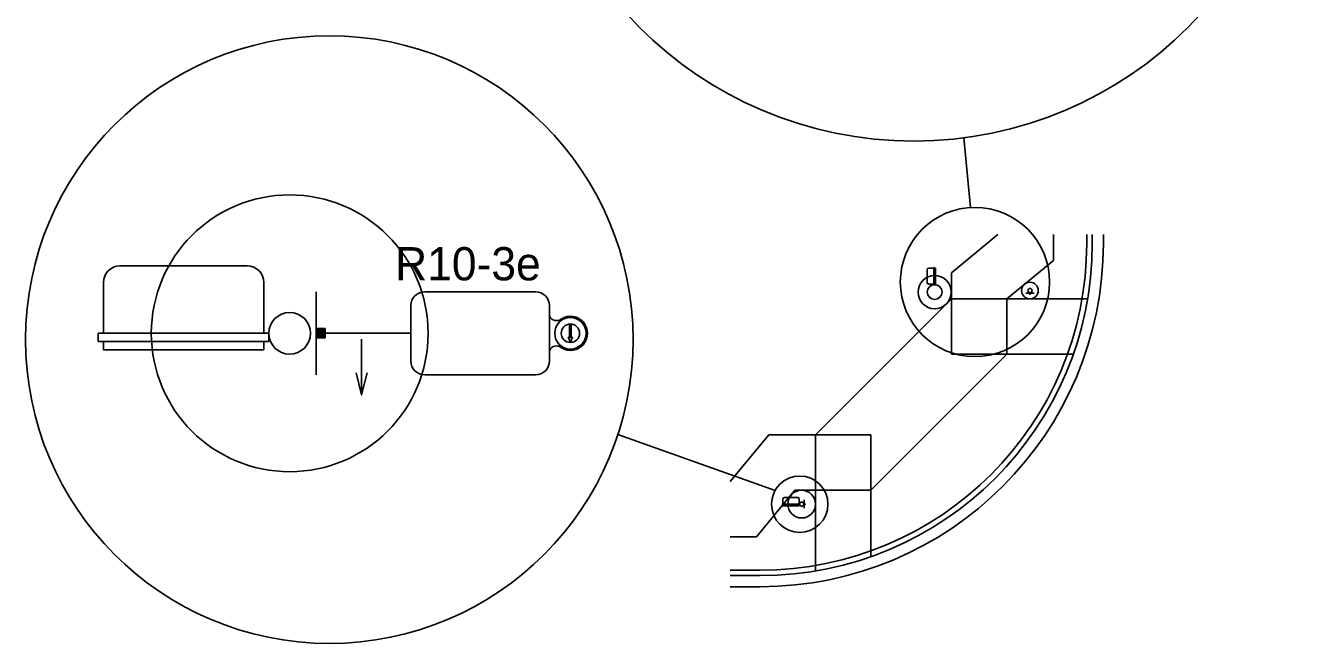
# Model space of a CAD drawing. Extents: x 1370050 to 1370716, y 380076 to 380502.
# Drawn here: x 1370417.2 to 1370532.5, y 380146.7 to 380202.5 of the extents above; entities that cross this region are included whole.
import ezdxf

# ---------------------------------------------------------------- set-up
doc = ezdxf.new("R2010")
doc.units = 0
doc.layers.add('T_Drafting', color=7, linetype='Continuous')

msp = doc.modelspace()

# ---------------------------------------------------------------- linework, layer by layer
at = {"layer": 'T_Drafting'}
for p, q in [((1370502.57, 380186.06), (1370501.97, 380192.36)), ((1370500.84, 380180.17), (1370505.04, 380183.62)), ((1370510.06, 380181.27), (1370510.06, 380183.62)), ((1370513.06, 380182.81), (1370513.06, 380183.62)), ((1370513.56, 380182.81), (1370513.56, 380183.62)), ((1370514.56, 380182.81), (1370514.56, 380183.62)), ((1370425.73, 380180.79), (1370437.23, 380180.79)), ((1370498.64, 380179.29), (1370498.64, 380180.44)), ((1370499.24, 380180.59), (1370498.79, 380180.59)), ((1370499.24, 380179.09), (1370499.24, 380180.63)), ((1370499.32, 380180.63), (1370499.24, 380180.63)), ((1370499.32, 380179.09), (1370499.32, 380180.63)), ((1370499.39, 380180.59), (1370499.32, 380180.59)), ((1370499.39, 380179.14), (1370499.39, 380180.59)), ((1370500.84, 380180.17), (1370500.84, 380172.81)), ((1370505.84, 380177.81), (1370510.06, 380181.27)), ((1370424.23, 380174.7), (1370424.23, 380179.29)), ((1370438.73, 380174.7), (1370438.73, 380179.29)), ((1370499.24, 380179.14), (1370498.79, 380179.14)), ((1370499.32, 380179.09), (1370499.24, 380179.09)), ((1370499.39, 380179.14), (1370499.32, 380179.14)), ((1370443.44, 380178.45), (1370443.44, 380170.95)), ((1370463.27, 380178.45), (1370453.26, 380178.45)), ((1370508.31, 380178.32), (1370507.56, 380178.32)), ((1370507.89, 380178.24), (1370507.89, 380178.32)), ((1370507.89, 380178.24), (1370507.97, 380178.32)), ((1370507.89, 380178.24), (1370507.97, 380178.32)), ((1370507.89, 380178.24), (1370507.97, 380178.32)), ((1370507.89, 380178.24), (1370507.97, 380178.32)), ((1370507.89, 380178.24), (1370507.97, 380178.32)), ((1370507.89, 380178.24), (1370507.97, 380178.32)), ((1370507.89, 380178.24), (1370507.97, 380178.32)), ((1370507.89, 380178.24), (1370507.97, 380178.32)), ((1370507.89, 380178.25), (1370507.97, 380178.32)), ((1370507.89, 380178.25), (1370507.96, 380178.32)), ((1370507.89, 380178.25), (1370507.96, 380178.32)), ((1370507.89, 380178.25), (1370507.96, 380178.32)), ((1370507.89, 380178.25), (1370507.96, 380178.32)), ((1370507.89, 380178.25), (1370507.96, 380178.32)), ((1370507.89, 380178.25), (1370507.96, 380178.32)), ((1370507.89, 380178.26), (1370507.96, 380178.32)), ((1370507.89, 380178.26), (1370507.95, 380178.32)), ((1370507.89, 380178.26), (1370507.95, 380178.32)), ((1370507.89, 380178.26), (1370507.95, 380178.32)), ((1370507.89, 380178.26), (1370507.95, 380178.32)), ((1370507.89, 380178.26), (1370507.95, 380178.32)), ((1370507.89, 380178.26), (1370507.95, 380178.32)), ((1370507.89, 380178.26), (1370507.95, 380178.32)), ((1370507.89, 380178.27), (1370507.94, 380178.32)), ((1370507.89, 380178.27), (1370507.94, 380178.32)), ((1370507.89, 380178.27), (1370507.94, 380178.32)), ((1370507.89, 380178.27), (1370507.94, 380178.32)), ((1370507.89, 380178.27), (1370507.94, 380178.32)), ((1370507.89, 380178.27), (1370507.94, 380178.32)), ((1370507.89, 380178.27), (1370507.94, 380178.32)), ((1370507.89, 380178.28), (1370507.93, 380178.32)), ((1370507.89, 380178.28), (1370507.93, 380178.32)), ((1370507.89, 380178.28), (1370507.93, 380178.32)), ((1370507.89, 380178.28), (1370507.93, 380178.32)), ((1370507.89, 380178.28), (1370507.93, 380178.32)), ((1370507.89, 380178.28), (1370507.93, 380178.32)), ((1370507.89, 380178.28), (1370507.93, 380178.32)), ((1370507.89, 380178.29), (1370507.92, 380178.32)), ((1370507.89, 380178.29), (1370507.92, 380178.32)), ((1370507.89, 380178.29), (1370507.92, 380178.32)), ((1370507.89, 380178.29), (1370507.92, 380178.32)), ((1370507.89, 380178.29), (1370507.92, 380178.32)), ((1370507.89, 380178.29), (1370507.92, 380178.32)), ((1370507.89, 380178.29), (1370507.92, 380178.32)), ((1370507.89, 380178.3), (1370507.91, 380178.32)), ((1370507.89, 380178.3), (1370507.91, 380178.32)), ((1370507.89, 380178.3), (1370507.91, 380178.32)), ((1370507.89, 380178.3), (1370507.91, 380178.32)), ((1370507.89, 380178.3), (1370507.91, 380178.32)), ((1370507.89, 380178.3), (1370507.91, 380178.32)), ((1370507.89, 380178.3), (1370507.91, 380178.32)), ((1370507.89, 380178.31), (1370507.91, 380178.32)), ((1370507.89, 380178.31), (1370507.9, 380178.32)), ((1370507.89, 380178.31), (1370507.9, 380178.32)), ((1370507.89, 380178.31), (1370507.9, 380178.32)), ((1370507.89, 380178.31), (1370507.9, 380178.32)), ((1370507.89, 380178.31), (1370507.9, 380178.32)), ((1370507.89, 380178.31), (1370507.9, 380178.32)), ((1370507.89, 380178.32), (1370507.9, 380178.32)), ((1370507.89, 380178.32), (1370507.89, 380178.32)), ((1370507.89, 380178.32), (1370507.89, 380178.32)), ((1370507.89, 380178.24), (1370507.97, 380178.24)), ((1370507.9, 380178.24), (1370507.97, 380178.32)), ((1370507.9, 380178.24), (1370507.97, 380178.31)), ((1370507.9, 380178.24), (1370507.97, 380178.31)), ((1370507.9, 380178.24), (1370507.97, 380178.31)), ((1370507.9, 380178.24), (1370507.97, 380178.31)), ((1370507.9, 380178.24), (1370507.97, 380178.31)), ((1370507.9, 380178.24), (1370507.97, 380178.31)), ((1370507.91, 380178.24), (1370507.97, 380178.31)), ((1370507.91, 380178.24), (1370507.97, 380178.3)), ((1370507.91, 380178.24), (1370507.97, 380178.3)), ((1370507.91, 380178.24), (1370507.97, 380178.3)), ((1370507.91, 380178.24), (1370507.97, 380178.3)), ((1370507.91, 380178.24), (1370507.97, 380178.3)), ((1370507.91, 380178.24), (1370507.97, 380178.3)), ((1370507.92, 380178.24), (1370507.97, 380178.3)), ((1370507.92, 380178.24), (1370507.97, 380178.29)), ((1370507.92, 380178.24), (1370507.97, 380178.29)), ((1370507.92, 380178.24), (1370507.97, 380178.29)), ((1370507.92, 380178.24), (1370507.97, 380178.29)), ((1370507.92, 380178.24), (1370507.97, 380178.29)), ((1370507.92, 380178.24), (1370507.97, 380178.29)), ((1370507.92, 380178.24), (1370507.97, 380178.29)), ((1370507.93, 380178.24), (1370507.97, 380178.28)), ((1370507.93, 380178.24), (1370507.97, 380178.28)), ((1370507.93, 380178.24), (1370507.97, 380178.28)), ((1370507.93, 380178.24), (1370507.97, 380178.28)), ((1370507.93, 380178.24), (1370507.97, 380178.28)), ((1370507.93, 380178.24), (1370507.97, 380178.28)), ((1370507.93, 380178.24), (1370507.97, 380178.28)), ((1370507.94, 380178.24), (1370507.97, 380178.27)), ((1370507.94, 380178.24), (1370507.97, 380178.27)), ((1370507.94, 380178.24), (1370507.97, 380178.27)), ((1370507.94, 380178.24), (1370507.97, 380178.27)), ((1370507.94, 380178.24), (1370507.97, 380178.27)), ((1370507.94, 380178.24), (1370507.97, 380178.27)), ((1370507.94, 380178.24), (1370507.97, 380178.27)), ((1370507.95, 380178.24), (1370507.97, 380178.26)), ((1370507.95, 380178.24), (1370507.97, 380178.26)), ((1370507.95, 380178.24), (1370507.97, 380178.26)), ((1370507.95, 380178.24), (1370507.97, 380178.26)), ((1370507.95, 380178.24), (1370507.97, 380178.26)), ((1370507.95, 380178.24), (1370507.97, 380178.26)), ((1370507.95, 380178.24), (1370507.97, 380178.26)), ((1370507.96, 380178.24), (1370507.97, 380178.25)), ((1370507.96, 380178.24), (1370507.97, 380178.25)), ((1370507.96, 380178.24), (1370507.97, 380178.25)), ((1370507.96, 380178.24), (1370507.97, 380178.25)), ((1370507.96, 380178.24), (1370507.97, 380178.25)), ((1370507.96, 380178.24), (1370507.97, 380178.25)), ((1370507.96, 380178.24), (1370507.97, 380178.25)), ((1370507.97, 380178.24), (1370507.97, 380178.32)), ((1370507.97, 380178.24), (1370507.97, 380178.25)), ((1370507.97, 380178.24), (1370507.97, 380178.24)), ((1370507.97, 380178.24), (1370507.97, 380178.24)), ((1370507.97, 380178.24), (1370507.97, 380178.24)), ((1370507.97, 380178.24), (1370507.97, 380178.24)), ((1370507.97, 380178.24), (1370507.97, 380178.24)), ((1370507.97, 380178.24), (1370507.97, 380178.24)), ((1370452.01, 380177.2), (1370452.01, 380172.2)), ((1370464.52, 380172.2), (1370464.52, 380177.2)), ((1370500.84, 380177.81), (1370488.56, 380165.52)), ((1370500.84, 380177.81), (1370513.14, 380177.81)), ((1370505.84, 380177.81), (1370505.84, 380172.81)), ((1370423.77, 380174.7), (1370439.19, 380174.7)), ((1370423.77, 380173.95), (1370423.77, 380174.7)), ((1370439.19, 380173.95), (1370439.19, 380174.7)), ((1370444.27, 380175.12), (1370443.44, 380175.12)), ((1370443.44, 380174.29), (1370444.27, 380175.12)), ((1370443.44, 380174.3), (1370444.26, 380175.12)), ((1370443.44, 380174.32), (1370444.24, 380175.12)), ((1370443.44, 380174.33), (1370444.23, 380175.12)), ((1370443.44, 380174.35), (1370444.21, 380175.12)), ((1370443.44, 380174.36), (1370444.2, 380175.12)), ((1370443.44, 380174.37), (1370444.18, 380175.12)), ((1370443.44, 380174.39), (1370444.17, 380175.12)), ((1370443.44, 380174.4), (1370444.16, 380175.12)), ((1370443.44, 380174.42), (1370444.14, 380175.12)), ((1370443.44, 380174.43), (1370444.13, 380175.12)), ((1370443.44, 380174.44), (1370444.11, 380175.12)), ((1370443.44, 380174.46), (1370444.1, 380175.12)), ((1370443.44, 380174.47), (1370444.09, 380175.12)), ((1370443.44, 380174.49), (1370444.07, 380175.12)), ((1370443.44, 380174.5), (1370444.06, 380175.12)), ((1370443.44, 380174.51), (1370444.04, 380175.12)), ((1370443.44, 380174.53), (1370444.03, 380175.12)), ((1370443.44, 380174.54), (1370444.01, 380175.12)), ((1370443.44, 380174.56), (1370444, 380175.12)), ((1370443.44, 380174.57), (1370443.99, 380175.12)), ((1370443.44, 380174.59), (1370443.97, 380175.12)), ((1370443.44, 380174.6), (1370443.96, 380175.12)), ((1370443.44, 380174.61), (1370443.94, 380175.12)), ((1370443.44, 380174.63), (1370443.93, 380175.12)), ((1370443.44, 380174.64), (1370443.92, 380175.12)), ((1370443.44, 380174.66), (1370443.9, 380175.12)), ((1370443.44, 380174.67), (1370443.89, 380175.12)), ((1370443.44, 380174.68), (1370443.87, 380175.12)), ((1370443.44, 380174.7), (1370443.86, 380175.12)), ((1370443.44, 380174.71), (1370443.84, 380175.12)), ((1370443.44, 380174.73), (1370443.83, 380175.12)), ((1370443.44, 380174.74), (1370443.82, 380175.12)), ((1370443.44, 380174.76), (1370443.8, 380175.12)), ((1370443.44, 380174.77), (1370443.79, 380175.12)), ((1370443.44, 380174.78), (1370443.77, 380175.12)), ((1370443.44, 380174.8), (1370443.76, 380175.12)), ((1370443.44, 380174.81), (1370443.75, 380175.12)), ((1370443.44, 380174.83), (1370443.73, 380175.12)), ((1370443.44, 380174.84), (1370443.72, 380175.12)), ((1370443.44, 380174.85), (1370443.7, 380175.12)), ((1370443.44, 380174.87), (1370443.69, 380175.12)), ((1370443.44, 380174.88), (1370443.68, 380175.12)), ((1370443.44, 380174.9), (1370443.66, 380175.12)), ((1370443.44, 380174.91), (1370443.65, 380175.12)), ((1370443.44, 380174.92), (1370443.63, 380175.12)), ((1370443.44, 380174.94), (1370443.62, 380175.12)), ((1370443.44, 380174.95), (1370443.6, 380175.12)), ((1370443.44, 380174.97), (1370443.59, 380175.12)), ((1370443.44, 380174.98), (1370443.58, 380175.12)), ((1370443.44, 380175), (1370443.56, 380175.12)), ((1370443.44, 380175.01), (1370443.55, 380175.12)), ((1370443.44, 380175.02), (1370443.53, 380175.12)), ((1370443.44, 380175.04), (1370443.52, 380175.12)), ((1370443.44, 380175.05), (1370443.51, 380175.12)), ((1370443.44, 380175.07), (1370443.49, 380175.12)), ((1370443.44, 380175.08), (1370443.48, 380175.12)), ((1370443.44, 380175.09), (1370443.46, 380175.12)), ((1370443.44, 380175.11), (1370443.45, 380175.12)), ((1370443.45, 380174.29), (1370444.27, 380175.11)), ((1370443.46, 380174.29), (1370444.27, 380175.09)), ((1370443.48, 380174.29), (1370444.27, 380175.08)), ((1370443.49, 380174.29), (1370444.27, 380175.07)), ((1370443.51, 380174.29), (1370444.27, 380175.05)), ((1370443.52, 380174.29), (1370444.27, 380175.04)), ((1370443.53, 380174.29), (1370444.27, 380175.02)), ((1370443.55, 380174.29), (1370444.27, 380175.01)), ((1370443.56, 380174.29), (1370444.27, 380174.99)), ((1370443.58, 380174.29), (1370444.27, 380174.98)), ((1370443.59, 380174.29), (1370444.27, 380174.97)), ((1370443.61, 380174.29), (1370444.27, 380174.95)), ((1370443.62, 380174.29), (1370444.27, 380174.94)), ((1370443.63, 380174.29), (1370444.27, 380174.92)), ((1370443.65, 380174.29), (1370444.27, 380174.91)), ((1370443.66, 380174.29), (1370444.27, 380174.9)), ((1370443.68, 380174.29), (1370444.27, 380174.88)), ((1370443.69, 380174.29), (1370444.27, 380174.87)), ((1370443.7, 380174.29), (1370444.27, 380174.85)), ((1370443.72, 380174.29), (1370444.27, 380174.84)), ((1370443.73, 380174.29), (1370444.27, 380174.82)), ((1370443.75, 380174.29), (1370444.27, 380174.81)), ((1370443.76, 380174.29), (1370444.27, 380174.8)), ((1370443.78, 380174.29), (1370444.27, 380174.78)), ((1370443.79, 380174.29), (1370444.27, 380174.77)), ((1370443.8, 380174.29), (1370444.27, 380174.75)), ((1370443.82, 380174.29), (1370444.27, 380174.74)), ((1370443.83, 380174.29), (1370444.27, 380174.73)), ((1370443.85, 380174.29), (1370444.27, 380174.71)), ((1370443.86, 380174.29), (1370444.27, 380174.7)), ((1370443.87, 380174.29), (1370444.27, 380174.68)), ((1370443.89, 380174.29), (1370444.27, 380174.67)), ((1370443.9, 380174.29), (1370444.27, 380174.66)), ((1370443.92, 380174.29), (1370444.27, 380174.64)), ((1370443.93, 380174.29), (1370444.27, 380174.63)), ((1370443.95, 380174.29), (1370444.27, 380174.61)), ((1370443.96, 380174.29), (1370444.27, 380174.6)), ((1370443.97, 380174.29), (1370444.27, 380174.58)), ((1370443.99, 380174.29), (1370444.27, 380174.57)), ((1370444, 380174.29), (1370444.27, 380174.56)), ((1370444.02, 380174.29), (1370444.27, 380174.54)), ((1370444.03, 380174.29), (1370444.27, 380174.53)), ((1370444.04, 380174.29), (1370444.27, 380174.51)), ((1370444.06, 380174.29), (1370444.27, 380174.5)), ((1370444.07, 380174.29), (1370444.27, 380174.49)), ((1370444.09, 380174.29), (1370444.27, 380174.47)), ((1370444.1, 380174.29), (1370444.27, 380174.46)), ((1370444.11, 380174.29), (1370444.27, 380174.44)), ((1370444.13, 380174.29), (1370444.27, 380174.43)), ((1370444.14, 380174.29), (1370444.27, 380174.41)), ((1370444.27, 380174.29), (1370444.27, 380175.12)), ((1370444.27, 380174.7), (1370452.01, 380174.7)), ((1370466.35, 380175.53), (1370466.5, 380175.53)), ((1370466.35, 380174.27), (1370466.35, 380175.53)), ((1370466.5, 380174.27), (1370466.5, 380175.53)), ((1370423.77, 380173.95), (1370439.19, 380173.95)), ((1370424.23, 380173.2), (1370424.23, 380173.95)), ((1370438.73, 380173.2), (1370438.73, 380173.95)), ((1370444.27, 380174.29), (1370443.44, 380174.29)), ((1370444.16, 380174.29), (1370444.27, 380174.4)), ((1370444.17, 380174.29), (1370444.27, 380174.39)), ((1370444.19, 380174.29), (1370444.27, 380174.37)), ((1370444.2, 380174.29), (1370444.27, 380174.36)), ((1370444.21, 380174.29), (1370444.27, 380174.34)), ((1370444.23, 380174.29), (1370444.27, 380174.33)), ((1370444.24, 380174.29), (1370444.27, 380174.32)), ((1370444.26, 380174.29), (1370444.27, 380174.3)), ((1370444.27, 380174.29), (1370444.27, 380174.29)), ((1370447.55, 380174.17), (1370447.55, 380169.14)), ((1370466.22, 380174.37), (1370466.42, 380173.87)), ((1370466.35, 380174.27), (1370466.22, 380174.37)), ((1370466.62, 380174.37), (1370466.42, 380173.87)), ((1370466.62, 380174.37), (1370466.5, 380174.27)), ((1370424.23, 380173.2), (1370438.73, 380173.2)), ((1370505.84, 380172.81), (1370493.56, 380160.52)), ((1370500.84, 380172.81), (1370511.84, 380172.81)), ((1370453.26, 380170.95), (1370463.27, 380170.95)), ((1370484.9, 380160.5), (1370470.71, 380165.55)), ((1370484.33, 380165.52), (1370480.86, 380161.31)), ((1370484.33, 380165.52), (1370493.56, 380165.52)), ((1370488.56, 380165.52), (1370488.56, 380153.23)), ((1370493.56, 380165.52), (1370493.56, 380154.52)), ((1370486.69, 380160.52), (1370483.22, 380156.31)), ((1370485.62, 380159.27), (1370485.62, 380159.73)), ((1370485.77, 380159.88), (1370486.92, 380159.88)), ((1370486.69, 380160.52), (1370493.56, 380160.52)), ((1370487.07, 380159.27), (1370487.07, 380159.73)), ((1370487.54, 380159.65), (1370487.54, 380158.9)), ((1370485.58, 380159.27), (1370487.12, 380159.27)), ((1370485.58, 380159.2), (1370485.58, 380159.27)), ((1370485.58, 380159.2), (1370487.12, 380159.2)), ((1370485.62, 380159.12), (1370485.62, 380159.2)), ((1370485.62, 380159.12), (1370487.07, 380159.12)), ((1370487.07, 380159.12), (1370487.07, 380159.2)), ((1370487.12, 380159.2), (1370487.12, 380159.27)), ((1370487.63, 380159.31), (1370487.54, 380159.31)), ((1370487.54, 380159.23), (1370487.63, 380159.31)), ((1370487.54, 380159.23), (1370487.63, 380159.31)), ((1370487.54, 380159.23), (1370487.62, 380159.31)), ((1370487.54, 380159.23), (1370487.62, 380159.31)), ((1370487.54, 380159.24), (1370487.62, 380159.31)), ((1370487.54, 380159.24), (1370487.62, 380159.31)), ((1370487.54, 380159.24), (1370487.62, 380159.31)), ((1370487.54, 380159.24), (1370487.62, 380159.31)), ((1370487.54, 380159.24), (1370487.62, 380159.31)), ((1370487.54, 380159.24), (1370487.61, 380159.31)), ((1370487.54, 380159.24), (1370487.61, 380159.31)), ((1370487.54, 380159.25), (1370487.61, 380159.31)), ((1370487.54, 380159.25), (1370487.61, 380159.31)), ((1370487.54, 380159.25), (1370487.61, 380159.31)), ((1370487.54, 380159.25), (1370487.61, 380159.31)), ((1370487.54, 380159.25), (1370487.61, 380159.31)), ((1370487.54, 380159.25), (1370487.6, 380159.31)), ((1370487.54, 380159.25), (1370487.6, 380159.31)), ((1370487.54, 380159.26), (1370487.6, 380159.31)), ((1370487.54, 380159.26), (1370487.6, 380159.31)), ((1370487.54, 380159.26), (1370487.6, 380159.31)), ((1370487.54, 380159.26), (1370487.6, 380159.31)), ((1370487.54, 380159.26), (1370487.6, 380159.31)), ((1370487.54, 380159.26), (1370487.59, 380159.31)), ((1370487.54, 380159.26), (1370487.59, 380159.31)), ((1370487.54, 380159.27), (1370487.59, 380159.31)), ((1370487.54, 380159.27), (1370487.59, 380159.31)), ((1370487.54, 380159.27), (1370487.59, 380159.31)), ((1370487.54, 380159.27), (1370487.59, 380159.31)), ((1370487.54, 380159.27), (1370487.59, 380159.31)), ((1370487.54, 380159.27), (1370487.58, 380159.31)), ((1370487.54, 380159.27), (1370487.58, 380159.31)), ((1370487.54, 380159.28), (1370487.58, 380159.31)), ((1370487.54, 380159.28), (1370487.58, 380159.31)), ((1370487.54, 380159.28), (1370487.58, 380159.31)), ((1370487.54, 380159.28), (1370487.58, 380159.31)), ((1370487.54, 380159.28), (1370487.58, 380159.31)), ((1370487.54, 380159.28), (1370487.57, 380159.31)), ((1370487.54, 380159.28), (1370487.57, 380159.31)), ((1370487.54, 380159.29), (1370487.57, 380159.31)), ((1370487.54, 380159.29), (1370487.57, 380159.31)), ((1370487.54, 380159.29), (1370487.57, 380159.31)), ((1370487.54, 380159.29), (1370487.57, 380159.31)), ((1370487.54, 380159.29), (1370487.57, 380159.31)), ((1370487.54, 380159.29), (1370487.56, 380159.31)), ((1370487.54, 380159.29), (1370487.56, 380159.31)), ((1370487.54, 380159.3), (1370487.56, 380159.31)), ((1370487.54, 380159.3), (1370487.56, 380159.31)), ((1370487.54, 380159.3), (1370487.56, 380159.31)), ((1370487.54, 380159.3), (1370487.56, 380159.31)), ((1370487.54, 380159.3), (1370487.56, 380159.31)), ((1370487.54, 380159.3), (1370487.55, 380159.31)), ((1370487.54, 380159.3), (1370487.55, 380159.31)), ((1370487.54, 380159.3), (1370487.55, 380159.31)), ((1370487.54, 380159.31), (1370487.55, 380159.31)), ((1370487.54, 380159.31), (1370487.55, 380159.31)), ((1370487.54, 380159.31), (1370487.55, 380159.31)), ((1370487.54, 380159.31), (1370487.55, 380159.31)), ((1370487.54, 380159.31), (1370487.55, 380159.31)), ((1370487.54, 380159.31), (1370487.54, 380159.31)), ((1370487.63, 380159.23), (1370487.54, 380159.23)), ((1370487.55, 380159.23), (1370487.63, 380159.31)), ((1370487.55, 380159.23), (1370487.63, 380159.31)), ((1370487.55, 380159.23), (1370487.63, 380159.31)), ((1370487.55, 380159.23), (1370487.63, 380159.31)), ((1370487.55, 380159.23), (1370487.63, 380159.31)), ((1370487.55, 380159.23), (1370487.63, 380159.3)), ((1370487.55, 380159.23), (1370487.63, 380159.3)), ((1370487.56, 380159.23), (1370487.63, 380159.3)), ((1370487.56, 380159.23), (1370487.63, 380159.3)), ((1370487.56, 380159.23), (1370487.63, 380159.3)), ((1370487.56, 380159.23), (1370487.63, 380159.3)), ((1370487.56, 380159.23), (1370487.63, 380159.3)), ((1370487.56, 380159.23), (1370487.63, 380159.29)), ((1370487.56, 380159.23), (1370487.63, 380159.29)), ((1370487.56, 380159.23), (1370487.63, 380159.29)), ((1370487.57, 380159.23), (1370487.63, 380159.29)), ((1370487.57, 380159.23), (1370487.63, 380159.29)), ((1370487.57, 380159.23), (1370487.63, 380159.29)), ((1370487.57, 380159.23), (1370487.63, 380159.29)), ((1370487.57, 380159.23), (1370487.63, 380159.29)), ((1370487.57, 380159.23), (1370487.63, 380159.28)), ((1370487.57, 380159.23), (1370487.63, 380159.28)), ((1370487.58, 380159.23), (1370487.63, 380159.28)), ((1370487.58, 380159.23), (1370487.63, 380159.28)), ((1370487.58, 380159.23), (1370487.63, 380159.28)), ((1370487.58, 380159.23), (1370487.63, 380159.28)), ((1370487.58, 380159.23), (1370487.63, 380159.28)), ((1370487.58, 380159.23), (1370487.63, 380159.27)), ((1370487.58, 380159.23), (1370487.63, 380159.27)), ((1370487.59, 380159.23), (1370487.63, 380159.27)), ((1370487.59, 380159.23), (1370487.63, 380159.27)), ((1370487.59, 380159.23), (1370487.63, 380159.27)), ((1370487.59, 380159.23), (1370487.63, 380159.27)), ((1370487.59, 380159.23), (1370487.63, 380159.27)), ((1370487.59, 380159.23), (1370487.63, 380159.26)), ((1370487.59, 380159.23), (1370487.63, 380159.26)), ((1370487.6, 380159.23), (1370487.63, 380159.26)), ((1370487.6, 380159.23), (1370487.63, 380159.26)), ((1370487.6, 380159.23), (1370487.63, 380159.26)), ((1370487.6, 380159.23), (1370487.63, 380159.26)), ((1370487.6, 380159.23), (1370487.63, 380159.26)), ((1370487.6, 380159.23), (1370487.63, 380159.25)), ((1370487.6, 380159.23), (1370487.63, 380159.25)), ((1370487.61, 380159.23), (1370487.63, 380159.25)), ((1370487.61, 380159.23), (1370487.63, 380159.25)), ((1370487.61, 380159.23), (1370487.63, 380159.25)), ((1370487.61, 380159.23), (1370487.63, 380159.25)), ((1370487.61, 380159.23), (1370487.63, 380159.25)), ((1370487.61, 380159.23), (1370487.63, 380159.24)), ((1370487.61, 380159.23), (1370487.63, 380159.24)), ((1370487.62, 380159.23), (1370487.63, 380159.24)), ((1370487.62, 380159.23), (1370487.63, 380159.24)), ((1370487.62, 380159.23), (1370487.63, 380159.24)), ((1370487.62, 380159.23), (1370487.63, 380159.24)), ((1370487.62, 380159.23), (1370487.63, 380159.24)), ((1370487.62, 380159.23), (1370487.63, 380159.23)), ((1370487.62, 380159.23), (1370487.63, 380159.23)), ((1370487.63, 380159.23), (1370487.63, 380159.31)), ((1370487.63, 380159.23), (1370487.63, 380159.23)), ((1370483.22, 380156.31), (1370480.86, 380156.31)), ((1370483.56, 380153.31), (1370480.86, 380153.31)), ((1370483.56, 380152.81), (1370480.86, 380152.81)), ((1370483.56, 380151.81), (1370480.86, 380151.81))]:
    msp.add_line(p, q, dxfattribs=at)
msp.add_lwpolyline([(1370448.05, 380171.14), (1370447.55, 380169.14), (1370447.05, 380171.14)], dxfattribs=at)
for centre, radius in [((1370497.43, 380227.09), 35.03), ((1370444.64, 380174.13), 27.44), ((1370441.06, 380174.7), 12.5), ((1370502.96, 380179.33), 6.74), ((1370499.32, 380178.42), 1.5), ((1370499.32, 380178.42), 0.667), ((1370507.93, 380178.56), 0.75), ((1370507.93, 380178.56), 0.19), ((1370441.06, 380174.7), 1.88), ((1370466.42, 380174.7), 1.42), ((1370466.42, 380174.7), 0.833), ((1370487.13, 380159.26), 2.55), ((1370487.31, 380159.27), 1.25), ((1370487.31, 380159.27), 0.188)]:
    msp.add_circle(centre, radius, dxfattribs=at)
for centre, radius, start, end in [((1370483.56, 380182.81), 30, 270, 0), ((1370483.56, 380182.81), 31, 270, 0), ((1370483.56, 380182.81), 29.5, 270, 0), ((1370425.73, 380179.29), 1.5, 90, 180), ((1370437.23, 380179.29), 1.5, 360, 90), ((1370498.79, 380180.44), 0.15, 90, 180), ((1370498.79, 380179.29), 0.15, 180, 270), ((1370453.26, 380177.2), 1.25, 90, 180), ((1370463.27, 380177.2), 1.25, 0, 90), ((1370465.16, 380176.54), 0.7, 205.1956, 311.8028), ((1370466.42, 380174.7), 1.54, 238.7402, 121.2598), ((1370466.42, 380174.7), 1.54, 42.5066, 121.2598), ((1370465.16, 380172.86), 0.7, 48.1972, 154.8044), ((1370466.42, 380174.7), 1.54, 238.7402, 317.4934), ((1370453.26, 380172.2), 1.25, 180, 270), ((1370463.27, 380172.2), 1.25, 270, 0), ((1370485.77, 380159.73), 0.15, 90, 180), ((1370486.92, 380159.73), 0.15, 360, 90)]:
    msp.add_arc(centre, radius, start, end, dxfattribs=at)

# ---------------------------------------------------------------- texts
msp.add_text('R10-3e', height=3, dxfattribs=at).set_placement((1370450.58, 380179.48))

doc.saveas('drawing.dxf')
